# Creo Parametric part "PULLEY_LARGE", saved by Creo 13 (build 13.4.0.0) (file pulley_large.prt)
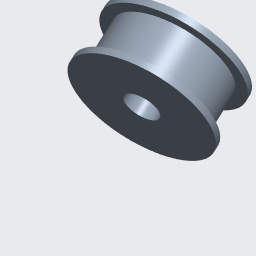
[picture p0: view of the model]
Units: millimeter Newton Second (mmNs); MM, TONNE, SECS

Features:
  1. datum plane "RIGHT"
  2. datum plane "TOP"
  3. datum plane "FRONT"
  4. coordinate system
  5. protrusion
  6. protrusion
  7. protrusion
  8. cut

Surfaces: 4 cylinder, 4 plane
